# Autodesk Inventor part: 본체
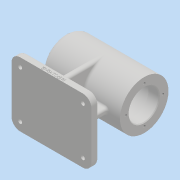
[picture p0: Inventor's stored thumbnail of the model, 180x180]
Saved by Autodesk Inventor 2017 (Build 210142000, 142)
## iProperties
Part Number: 본체
Material: 일반
Document SubType Name: Modeling
Designer: mrc
Density: 1 g/cm^3
Appearance: 기본값
Author: mrc
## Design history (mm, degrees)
sketch "스케치1"
  geometry: L1 (56, 21)-(56, 34); L2 (56, 34)-(-56, 34); L3 (-56, 34)-(-56, 0); L4 (-56, 0)-(56, 0); L5 (-56, 0)-(-50, 0); L6 (-50, 10.5)-(-47, 10.5); L7 (-47, 10.5)-(-47, 16); L8 (-47, 16)-(-43, 16); L9 (-43, 16)-(-43, 17.5); L10 (-43, 17.5)-(-25, 17.5); L11 (-25, 17.5)-(-25, 21); L12 (-25, 21)-(-13, 21); L13 (-13, 21)-(-13, 24); L14 (-13, 24)-(41, 24); L15 (41, 24)-(41, 21); L16 (41, 21)-(56, 21); L17 (-50, 10.5)-(-50, 0); 2 further points
  constraints: 34 end point, 12 perpendicular, 2 horizontal, 2 midpoint, 2 point on line, 2 vertical, 1 vertical alignment
  dimensions: "d0" = 112 distance of L1.end L2.end; "d1" = 68 diameter of L2 L4; "d11" = 42 diameter of L16 L4; "d12" = 48 diameter of L14 L4; "d13" = 21 diameter of L6 L4; "d14" = 32 diameter of L8 L4; "d15" = 35 diameter of L10 L4; "d16" = 15 distance between parallel lines of L1 L15; "d17" = 54 distance between parallel lines of L13 L15; "d18" = 12 distance between parallel lines of L11 L13; "d19" = 18 distance between parallel lines of L9 L11; "d20" = 4 distance between parallel lines of L7 L9; "d21" = 3 distance between parallel lines of L17 L7
revolve "회전1" sketch "스케치1" stored, may be unused: angle "d22" = 90 deg
sketch "스케치2"
  geometry: L1 (-56, -64)-(56, -64); L2 (56, -64)-(56, -74); L3 (56, -74)-(-56, -74); L4 (-56, -74)-(-56, -64); 2 further points
  constraints: 8 end point, 2 parallel, 1 horizontal, 1 midpoint, 1 perpendicular, 1 vertical alignment
  dimensions: "d23" = 112 distance of L2.end L3.end; "d24" = 10 distance of L1.end L2.end; "d25" = 74 distance from line of point (0, 0) L3
extrude "돌출1" join sketch "스케치2" stored distance "d26" = 90; taper "d27" = 0 deg
sketch "스케치3"
  geometry: L1 (52, 41)-(60, 41); L2 (60, 41)-(60, 49); L3 (60, 49)-(52, 49); L4 (52, 49)-(52, 41); L5 (52, 41)-(60, 49); L6 (60, 41)-(52, 49); 1 further point
  constraints: 12 end point, 2 midpoint, 2 parallel, 1 horizontal, 1 perpendicular
  dimensions: "d28" = 8 distance of L2.end L3.end; "d29" = 8 distance of L1.end L2.end
extrude "돌출2" join sketch "스케치3" stored distance "d30" = 90; taper "d31" = 0 deg
sketch "스케치4"
  geometry: L1 (-38, -43.025)-(-38, -55.287); L2 (38, -43.025)-(38, -52.686); L3 (-56, -64)-(-56, -74) reference; L4 (56, -74)-(56, -64) reference; 1 further point
  constraints: 4 end point, 2 vertical
  dimensions: "d32" = 18 distance between parallel lines of L3 L1; "d33" = 18 distance between parallel lines of L4 L2
feature "리브1" dims "d34" = 1, "d35" = 8, "d36" = 0, "d37" = 0, "d38" = 1, "d39" = 1
feature "리브2" dims "d40" = 1, "d41" = 8, "d42" = 0, "d43" = 0, "d44" = 1, "d45" = 1
sketch "스케치5"
  geometry: L1 (-13.285, 34)-(-45.587, 34); L2 (-16.672, -34)-(-45.587, -34); C1 r 34 at (0, 0) reference; 1 further point
  constraints: 4 end point, 2 horizontal, 2 tangent
feature "리브3" dims "d46" = 1, "d47" = 8, "d48" = 0, "d49" = 0, "d50" = 1, "d51" = 1
feature "리브4" dims "d52" = 1, "d53" = 8, "d54" = 0, "d55" = 0, "d56" = 1, "d57" = 1
sketch "스케치6"
  geometry: L1 (0, 0)-(0, 90) reference; L2 (112, 90)-(0, 90) reference; L3 (112, 0)-(112, 90) reference; L4 (0, 0)-(112, 0) reference; 5 further points
  constraints: 2 horizontal alignment, 2 vertical alignment
  dimensions: "d58" = 12 distance from line of L1 point (12, 78); "d59" = 12 distance from line of L2 point (12, 78); "d60" = 12 distance from line of L3 point (100, 78); "d61" = 12 distance from line of L4 point (12, 12)
hole "구멍1" sketch "스케치6" at (12, 78), (100, 78), (100, 12), (12, 12) diameter "d62" = 5.5; stored, may be unused: countersink angle "d66" = 90 deg, drill point angle "d68" = 118 deg; dims "d63" = 6, "d64" = 9.5, "d65" = 5.4, "d67" = 8
sketch "스케치7"
  geometry: 2 further points
  constraints: 1 vertical alignment
  dimensions: "d69" = 26 distance of point (0, 26) point (0, 0)
hole "구멍2" sketch "스케치7" at (0, 26) diameter "d70" = 3.242; stored, may be unused: countersink angle "d74" = 90 deg, drill point angle "d76" = 118 deg; dims "d71" = 8, "d72" = 9.5, "d73" = 5.4, "d75" = 11
fillet "모깎기1" dims "d80" = 10, "d81" = 12
fillet "모깎기2" dims "d82" = 3
fillet "모깎기3" dims "d83" = 3
fillet "모깎기4" dims "d84" = 3, "d85" = 0.3
chamfer "모따기1" distance "d86" = 1; stored, may be unused: second distance "d87" = 2, angle "d88" = 45 deg
sketch "스케치8"
  geometry: L1 (56, -74)-(56, -67) reference; L2 (56, -74)-(44, -74) reference; 2 further points
  constraints: 1 other
  dimensions: "d89" = 56 distance from line of L1 point (0, -71); "d90" = 3 distance from line of L2 point (0, -71)
feature "엠보싱1" sketch "스케치8" dims "d0" = 112, "d91" = 0.5, "d92" = 0
node "솔리드1"
pattern_circular "원형 패턴1" dims angle "d78" = 360 deg
